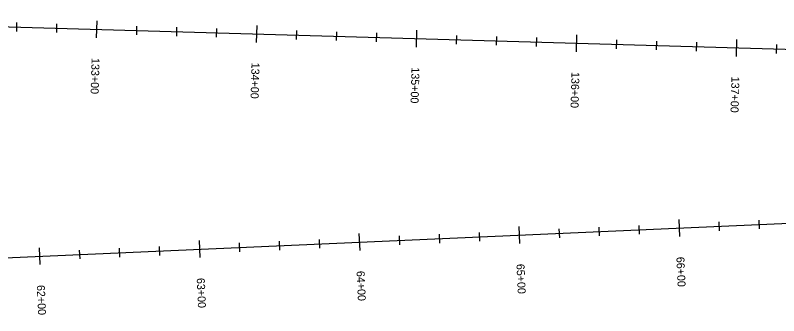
# Model space of a CAD drawing. Extents: x 2300830 to 2307917, y 756066 to 766359.
# Drawn here: x 2305041.8 to 2305518.9, y 760710.4 to 760898.1 of the extents above; entities that cross this region are included whole.
import ezdxf

# ---------------------------------------------------------------- set-up
doc = ezdxf.new("R2010")
doc.units = 0
for name, color, linetype in [('Default', 7, 'Continuous'), ('Draft_Station Labels Major', 7, 'Continuous'), ('Draft_Station Ticks Major', 7, 'Continuous'), ('Draft_Station Ticks Minor', 7, 'Continuous'), ('Geom_Baseline', 7, 'Continuous')]:
    doc.layers.add(name, color=color, linetype=linetype)

msp = doc.modelspace()

# ---------------------------------------------------------------- linework, layer by layer
at = {"layer": 'Default'}
for p, q in [((2304792.64, 760898.13), (2307906.67, 760807.43)), ((2304212.98, 760710.44), (2305828.49, 760781.61))]:
    msp.add_line(p, q, dxfattribs=at)
at = {"layer": 'Draft_Station Ticks Major'}
for p, q in [((2305092.71, 760894.73), (2305092.4, 760884.12)), ((2305192.67, 760891.82), (2305192.36, 760881.21)), ((2305292.63, 760888.91), (2305292.32, 760878.3)), ((2305392.59, 760886), (2305392.28, 760875.38)), ((2305492.54, 760883.09), (2305492.23, 760872.47)), ((2305456.36, 760770.56), (2305456.82, 760759.95)), ((2305356.45, 760766.16), (2305356.92, 760755.55)), ((2305256.55, 760761.76), (2305257.02, 760751.15)), ((2305156.65, 760757.35), (2305157.12, 760746.75)), ((2305056.74, 760752.95), (2305057.21, 760742.34))]:
    msp.add_line(p, q, dxfattribs=at)
at = {"layer": 'Draft_Station Ticks Minor'}
for p, q in [((2305042.66, 760893.61), (2305042.5, 760888.09)), ((2305067.65, 760892.88), (2305067.49, 760887.37)), ((2305117.63, 760891.43), (2305117.47, 760885.91)), ((2305142.62, 760890.7), (2305142.46, 760885.18)), ((2305167.61, 760889.97), (2305167.45, 760884.45)), ((2305217.59, 760888.52), (2305217.42, 760883)), ((2305242.57, 760887.79), (2305242.41, 760882.27)), ((2305267.56, 760887.06), (2305267.4, 760881.54)), ((2305317.54, 760885.6), (2305317.38, 760880.09)), ((2305342.53, 760884.88), (2305342.37, 760879.36)), ((2305367.52, 760884.15), (2305367.36, 760878.63)), ((2305417.5, 760882.69), (2305417.34, 760877.18)), ((2305442.49, 760881.97), (2305442.33, 760876.45)), ((2305467.48, 760881.24), (2305467.32, 760875.72)), ((2305517.46, 760879.78), (2305517.3, 760874.26)), ((2305481.45, 760769.08), (2305481.69, 760763.57)), ((2305506.42, 760770.18), (2305506.67, 760764.67)), ((2305381.54, 760764.68), (2305381.79, 760759.16)), ((2305406.52, 760765.78), (2305406.76, 760760.27)), ((2305431.49, 760766.88), (2305431.74, 760761.37)), ((2305281.64, 760760.28), (2305281.88, 760754.76)), ((2305306.62, 760761.38), (2305306.86, 760755.86)), ((2305331.59, 760762.48), (2305331.83, 760756.96)), ((2305181.74, 760755.88), (2305181.98, 760750.36)), ((2305206.71, 760756.98), (2305206.96, 760751.46)), ((2305231.69, 760758.08), (2305231.93, 760752.56)), ((2305081.83, 760751.48), (2305082.08, 760745.96)), ((2305106.81, 760752.58), (2305107.05, 760747.06)), ((2305131.79, 760753.68), (2305132.03, 760748.16))]:
    msp.add_line(p, q, dxfattribs=at)
at = {"layer": 'Geom_Baseline'}
for p, q in [((2304792.64, 760898.13), (2307906.67, 760807.43)), ((2304212.98, 760710.44), (2305828.49, 760781.61))]:
    msp.add_line(p, q, dxfattribs=at)

# ---------------------------------------------------------------- texts
at = {"layer": 'Draft_Station Labels Major'}
for s, rotation, p in [('133+00', 268.3316, (2305089.54, 760871.48)), ('134+00', 268.3316, (2305189.49, 760868.57)), ('135+00', 268.3316, (2305289.45, 760865.65)), ('136+00', 268.3316, (2305389.41, 760862.74)), ('137+00', 268.3316, (2305489.37, 760859.83)), ('66+00', 272.5224, (2305454.89, 760747.13)), ('65+00', 272.5224, (2305354.98, 760742.73)), ('64+00', 272.5224, (2305255.08, 760738.33)), ('63+00', 272.5224, (2305155.18, 760733.93)), ('62+00', 272.5224, (2305055.27, 760729.53))]:
    msp.add_text(s, height=5, rotation=rotation, dxfattribs=at).set_placement(p)

doc.saveas('drawing.dxf')
